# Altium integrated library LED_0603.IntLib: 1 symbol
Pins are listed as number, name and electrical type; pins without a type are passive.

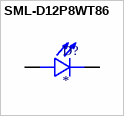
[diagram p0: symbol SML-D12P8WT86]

## SML-D12P8WT86
designator D?
Green 560nm LED Indication - Discrete 2.2V 0603 (1608 Metric); MF: Rohm; MP: SML-D12P8WT86
footprint LED_SML-D12P8WT86
pins: A, C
